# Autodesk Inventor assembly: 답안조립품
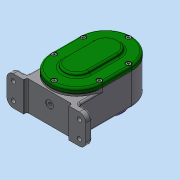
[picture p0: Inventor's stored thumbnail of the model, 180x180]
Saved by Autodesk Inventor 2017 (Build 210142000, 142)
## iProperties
Part Number: 답안조립품
Material: 일반
Document SubType Name: Assembly
Designer: MRC
Author: MRC
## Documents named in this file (19)
- C:\Users\MRC\Desktop\답안조립품.iam
- C:\Users\MRC\Desktop\710609V1005\본체.ipt
- C:\Users\MRC\Desktop\710609V1005\개스킷 A.ipt
- C:\Users\MRC\Desktop\710609V1005\개스킷 B.ipt
- C:\Users\MRC\Desktop\710609V1005\베어링 6001.ipt
- 베어링 6001.ipt
- C:\Users\MRC\Desktop\710609V1005\베어링 6002.ipt
- 베어링 6002.ipt
- C:\Users\MRC\Desktop\710609V1005\볼트 M4.ipt
- C:\Users\MRC\Desktop\710609V1005\스퍼기어 A.ipt
- C:\Users\MRC\Desktop\710609V1005\스퍼기어 B.ipt
- C:\Users\MRC\Desktop\710609V1005\오일 실 12 22 7.ipt
- C:\Users\MRC\Desktop\710609V1005\축 A.ipt
- C:\Users\MRC\Desktop\710609V1005\축 B.ipt
- C:\Users\MRC\Desktop\710609V1005\칼라.ipt
- C:\Users\MRC\Desktop\710609V1005\커버 A.ipt
- C:\Users\MRC\Desktop\710609V1005\커버 B.ipt
- C:\Users\MRC\Desktop\710609V1005\키 4 x 4 x 12.ipt
- C:\Users\MRC\Desktop\710609V1005\키 5 x 5 x 12.ipt
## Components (2 placed, 2 different names)
1. 개스킷 A:1
2. 개스킷 B:1
